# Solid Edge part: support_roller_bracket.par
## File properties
Title: Solid Edge 20
Author: vicky raina
Template: Normal.par
Last saved by: Robert a Rhodes jr
Revision: 15
Application: Solid Edge
Material: aluminum
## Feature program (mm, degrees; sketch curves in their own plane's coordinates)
sketch for "unnamed Protrusion 1" #1 plane through (0, 0, 0) normal (0, -1, 0) x-axis (1, 0, 0)
  circle centre (0, -138.9237) radius 3.81
sketch for "unnamed Protrusion 1" #2 plane through (0, 0, 0) normal (0, -1, 0) x-axis (1, 0, 0)
  line (143.637, -99.9249) -> (-143.637, -99.9249)
  line (-143.637, -99.9249) -> (-143.637, -115.1647)
  line (-143.637, -115.1647) -> (-61.0846, -156.7704)
  line (-61.0846, -156.7704) -> (-61.0846, -162.9363)
  line (-61.0846, -162.9363) -> (61.0846, -162.9363)
  line (61.0846, -156.7704) -> (61.0846, -162.9363)
  line (143.637, -115.1647) -> (61.0846, -156.7704)
  line (143.637, -99.9249) -> (143.637, -115.1647)
  dimension (linear) = 143.637
extrude "unnamed Protrusion 1" add finite 101.6 symmetric
fillet "unnamed Round 1"
fillet "unnamed Round 2"
sketch for "unnamed Protrusion 2" plane through (0, 0, 67.2512) normal (1, 0, 0) x-axis (0, 1, 0)
  arc centre (-23.4135, -61.792) radius 19.05 from (-23.4135, -42.742) to (-42.405, -60.3002) ccw
  line (-50.8, -167.1761) -> (-42.405, -60.3002)
  line (-50.8, -167.1761) -> (50.8, -167.1761)
  line (45.7777, -60.8928) -> (50.8, -167.1761)
  arc centre (26.749, -61.792) radius 19.05 from (26.749, -42.742) to (45.7777, -60.8928) cw
  line (19.05, -42.742) -> (26.749, -42.742)
  line (19.05, -64.967) -> (19.05, -42.742)
  arc centre (0, -64.967) radius 19.05 from (-19.05, -64.967) to (19.05, -64.967) ccw
  line (-19.05, -42.742) -> (-19.05, -64.967)
  line (-23.4135, -42.742) -> (-19.05, -42.742)
extrude "unnamed Protrusion 2" add to key point symmetric
sketch for "unnamed Cutout 1" plane through (0, 0, 0) normal (0, -1, 0) x-axis (1, 0, 0)
  line (-128.3193, 24.5092) -> (125.6319, 24.5092)
  line (125.6319, 24.5092) -> (125.6319, -99.9249)
  line (125.6319, -99.9249) -> (-128.3193, -99.9249)
  line (-128.3193, -99.9249) -> (-128.3193, 24.5092)
extrude "unnamed Cutout 1" cut finite 203.2 symmetric
chamfer "unnamed Chamfer 1"
rib "unnamed Rib 1"
mirror "unnamed Mirror 1" of "unnamed Rib 1" about plane through (0, 0, 0) normal (1, 0, 0)
rib "unnamed Rib 2"
sketch for "unnamed Hole 1" plane through (0.1259, 0, -162.9363) normal (0, 0, -1) x-axis (-1, 0, 0)
  hole centre (0.1259, 0) bore radius 25.4
hole "unnamed Hole 1" through
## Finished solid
Body 1: solid body, 55 faces, 142 edges, 86 vertices.
  Faces by surface: plane 38, cylinder 17
  Edges by curve: line 106, circle 34, intersection 2
Bounding box of the edges (mm): 379.121 x 101.600 x 187.446, from (-189.5605, -50.8, -162.9363) to (189.5605, 50.8, 24.5092).
Cylindrical faces by radius (mm): R3.81 x2, R6.35 x2, R19.05 x6, R25.4 x1, R31.75 x4, R55.372 x2
Planar faces by outward normal: +x 4, +y 5, +z 5, -x 4, -y 5, -z 1, oblique 14
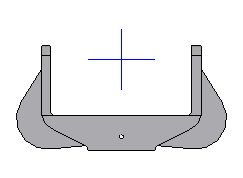
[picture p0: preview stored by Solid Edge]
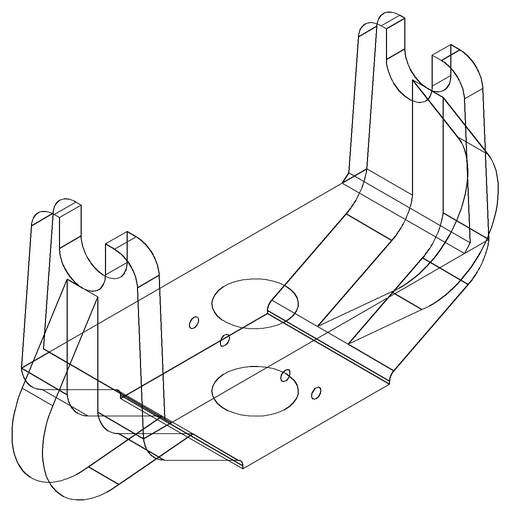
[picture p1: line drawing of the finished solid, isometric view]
